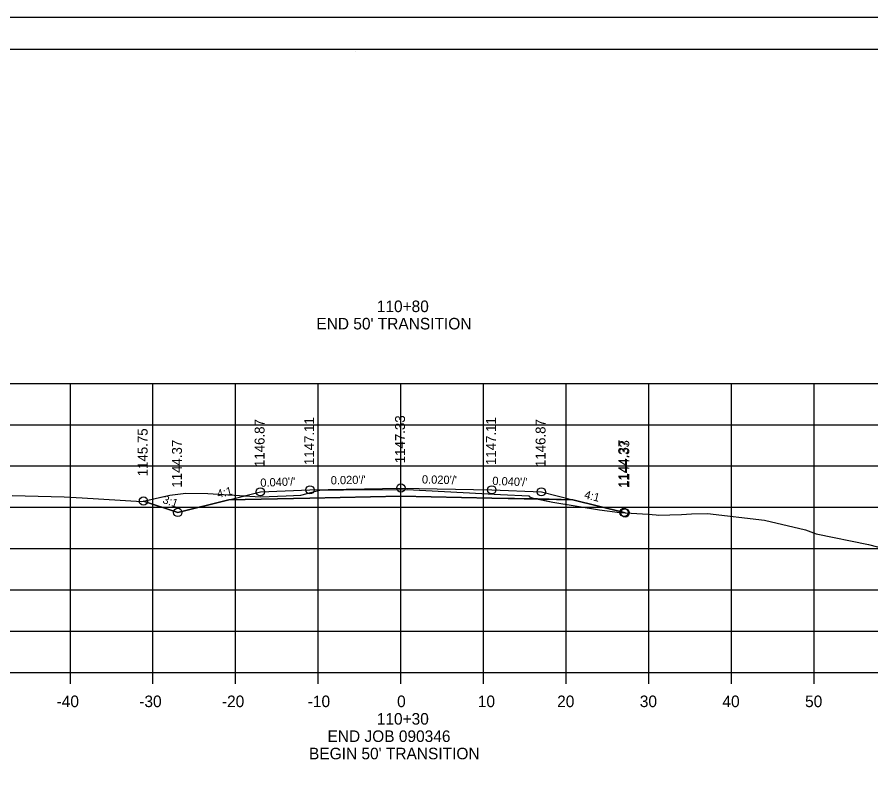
# Model space of a CAD drawing. Extents: x 1368971 to 1374497, y 378717 to 381839.
# Drawn here: x 1369095.2 to 1369198.5, y 381143 to 381234.8 of the extents above; entities that cross this region are included whole.
import ezdxf

# ---------------------------------------------------------------- set-up
doc = ezdxf.new("R2010")
doc.units = 0
for name, color, linetype in [('R_Alt Surface', 7, 'Continuous'), ('R_Axis', 7, 'Continuous'), ('R_Axis Annot', 7, 'Continuous'), ('R_Border', 7, 'Continuous'), ('R_Contours', 7, 'Continuous'), ('R_Exist Surface', 7, 'Continuous'), ('R_Fin Surface', 7, 'Continuous'), ('R_Grid', 7, 'Continuous'), ('R_No Plot', 7, 'Continuous'), ('R_Xsect Elev', 7, 'Continuous'), ('R_Xsect Slope', 7, 'Continuous')]:
    doc.layers.add(name, color=color, linetype=linetype)

msp = doc.modelspace()

# ---------------------------------------------------------------- linework, layer by layer
at = {"layer": 'R_Alt Surface'}
msp.add_lwpolyline([(1369120.77, 381176.35), (1369130.6, 381176.55), (1369141.6, 381176.77), (1369152.6, 381176.55), (1369162.42, 381176.35)], dxfattribs=at)
at = {"layer": 'R_Axis'}
for p, q in [((1369001.6, 381155.44), (1369281.6, 381155.44)), ((1369101.6, 381154.04), (1369101.6, 381155.44)), ((1369111.6, 381154.04), (1369111.6, 381155.44)), ((1369121.6, 381154.04), (1369121.6, 381155.44)), ((1369131.6, 381154.04), (1369131.6, 381155.44)), ((1369141.6, 381154.04), (1369141.6, 381155.44)), ((1369151.6, 381154.04), (1369151.6, 381155.44)), ((1369161.6, 381154.04), (1369161.6, 381155.44)), ((1369171.6, 381154.04), (1369171.6, 381155.44)), ((1369181.6, 381154.04), (1369181.6, 381155.44)), ((1369191.6, 381154.04), (1369191.6, 381155.44))]:
    msp.add_line(p, q, dxfattribs=at)
at = {"layer": 'R_Border'}
for p, q in [((1368983.6, 381230.9), (1369299.78, 381230.9)), ((1369136.12, 381230.64), (1369136.12, 381230.64)), ((1369136.12, 381230.64), (1369136.12, 381230.64))]:
    msp.add_line(p, q, dxfattribs=at)
at = {"layer": 'R_Contours'}
for points in [[(1369110.45, 381176.19), (1369113.65, 381176.9), (1369115.57, 381177.15), (1369118.24, 381177.11), (1369124.62, 381176.72), (1369127.7, 381176.83), (1369129.49, 381176.91), (1369131.48, 381177.43), (1369131.81, 381177.49), (1369134.65, 381177.54), (1369142.35, 381177.61), (1369153.66, 381176.98), (1369157.09, 381176.81), (1369157.18, 381176.69), (1369157.61, 381176.56), (1369158.15, 381176.44), (1369152.6, 381176.55), (1369141.6, 381176.77), (1369130.6, 381176.55), (1369120.77, 381176.35), (1369114.6, 381174.81)], [(1369158.15, 381176.44), (1369160, 381176.04), (1369165.64, 381175.14), (1369168.11, 381174.8), (1369168.73, 381174.76), (1369168.6, 381174.81), (1369162.42, 381176.35)]]:
    msp.add_lwpolyline(points, close=True, dxfattribs=at)
at = {"layer": 'R_Exist Surface'}
msp.add_lwpolyline([(1369094.55, 381176.88), (1369100.87, 381176.7), (1369103.02, 381176.59), (1369110.26, 381176.15), (1369113.65, 381176.9), (1369115.57, 381177.15), (1369118.24, 381177.11), (1369124.62, 381176.72), (1369127.7, 381176.83), (1369129.49, 381176.91), (1369131.48, 381177.43), (1369131.81, 381177.49), (1369134.65, 381177.54), (1369142.35, 381177.61), (1369153.66, 381176.98), (1369157.09, 381176.81), (1369157.18, 381176.69), (1369157.61, 381176.56), (1369160, 381176.04), (1369165.64, 381175.14), (1369168.11, 381174.8), (1369171.51, 381174.61), (1369172.51, 381174.54), (1369172.75, 381174.49), (1369175.55, 381174.56), (1369176.76, 381174.63), (1369178.72, 381174.68), (1369185.61, 381173.87), (1369190.58, 381172.72), (1369191.85, 381172.24), (1369198.17, 381170.93), (1369203.03, 381169.68)], dxfattribs=at)
at = {"layer": 'R_Fin Surface'}
msp.add_lwpolyline([(1369110.45, 381176.19), (1369114.6, 381174.81), (1369120.77, 381176.35), (1369124.6, 381177.31), (1369130.6, 381177.55), (1369141.6, 381177.77), (1369152.6, 381177.55), (1369158.6, 381177.31), (1369162.42, 381176.35), (1369168.6, 381174.81), (1369168.73, 381174.76)], dxfattribs=at)
at = {"layer": 'R_Grid'}
for p, q in [((1369001.6, 381190.44), (1369281.6, 381190.44)), ((1369101.6, 381155.44), (1369101.6, 381190.44)), ((1369111.6, 381155.44), (1369111.6, 381190.44)), ((1369121.6, 381155.44), (1369121.6, 381190.44)), ((1369131.6, 381155.44), (1369131.6, 381190.44)), ((1369141.6, 381155.44), (1369141.6, 381190.44)), ((1369151.6, 381155.44), (1369151.6, 381190.44)), ((1369161.6, 381155.44), (1369161.6, 381190.44)), ((1369171.6, 381155.44), (1369171.6, 381190.44)), ((1369181.6, 381155.44), (1369181.6, 381190.44)), ((1369191.6, 381155.44), (1369191.6, 381190.44)), ((1369001.6, 381185.44), (1369281.6, 381185.44)), ((1369001.6, 381180.44), (1369281.6, 381180.44)), ((1369001.6, 381175.44), (1369281.6, 381175.44)), ((1369001.6, 381170.44), (1369281.6, 381170.44)), ((1369001.6, 381165.44), (1369281.6, 381165.44)), ((1369001.6, 381160.44), (1369281.6, 381160.44)), ((1369001.6, 381155.44), (1369281.6, 381155.44))]:
    msp.add_line(p, q, dxfattribs=at)
at = {"layer": 'R_No Plot'}
msp.add_line((1368971.2, 381234.79), (1369304.53, 381234.79), dxfattribs=at)
for points in [[(1368971.19, 381234.79), (1369304.53, 381234.79), (1369304.53, 381021.46), (1368971.19, 381021.46)], [(1369217.52, 381230.9), (1369217.52, 381221.02), (1369253.25, 381221.02), (1369253.25, 381218.1), (1369276.45, 381218.1), (1369276.45, 381194.89), (1369299.78, 381194.89), (1369299.78, 381025.44), (1368983.6, 381025.44), (1368983.6, 381230.9)]]:
    msp.add_lwpolyline(points, close=True, dxfattribs=at)
for centre in [(1369124.6, 381177.31), (1369130.6, 381177.55), (1369141.6, 381177.77), (1369152.6, 381177.55), (1369158.6, 381177.31), (1369110.45, 381176.19), (1369114.6, 381174.81), (1369168.6, 381174.81), (1369168.73, 381174.76)]:
    msp.add_circle(centre, 0.5, dxfattribs=at)

# ---------------------------------------------------------------- texts
at = {"layer": 'R_Axis Annot'}
for s, p in [('110+80', (1369138.68, 381199.07)), ("END 50' TRANSITION", (1369131.37, 381196.97)), ('-40', (1369099.94, 381151.24)), ('-30', (1369109.94, 381151.24)), ('-20', (1369119.94, 381151.24)), ('-10', (1369130.33, 381151.24)), ('0', (1369141.14, 381151.24)), ('10', (1369150.91, 381151.24)), ('20', (1369160.51, 381151.24)), ('30', (1369170.51, 381151.24)), ('40', (1369180.51, 381151.24)), ('50', (1369190.51, 381151.24)), ('110+30', (1369138.68, 381149.12)), ('END JOB 090346', (1369132.72, 381147.02)), ("BEGIN 50' TRANSITION", (1369130.48, 381144.92))]:
    msp.add_text(s, height=1.4, dxfattribs=at).set_placement(p)
at = {"layer": 'R_Xsect Elev'}
for s, p in [('1146.87', (1369125.1, 381180.31)), ('1147.11', (1369131.1, 381180.55)), ('1147.33', (1369142.1, 381180.77)), ('1147.11', (1369153.1, 381180.55)), ('1146.87', (1369159.1, 381180.31)), ('1145.75', (1369110.95, 381179.19)), ('1144.37', (1369115.1, 381177.81)), ('1144.37', (1369169.1, 381177.81)), ('1144.33', (1369169.23, 381177.76))]:
    msp.add_text(s, height=1.2, rotation=90, dxfattribs=at).set_placement(p)
at = {"layer": 'R_Xsect Slope'}
for s, rotation, p in [("0.040'/'", 2.2906, (1369124.61, 381177.91)), ("0.020'/'", 1.1458, (1369133.12, 381178.2)), ("0.020'/'", 358.8542, (1369144.14, 381178.32)), ("0.040'/'", 357.7094, (1369152.65, 381178.15)), ('4:1', 14.0362, (1369119.48, 381176.54)), ('3:1', 341.5651, (1369112.68, 381175.97)), ('4:1', 345.9638, (1369163.72, 381176.54))]:
    msp.add_text(s, height=1, rotation=rotation, dxfattribs=at).set_placement(p)

doc.saveas('drawing.dxf')
